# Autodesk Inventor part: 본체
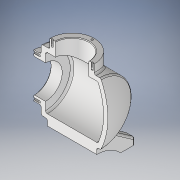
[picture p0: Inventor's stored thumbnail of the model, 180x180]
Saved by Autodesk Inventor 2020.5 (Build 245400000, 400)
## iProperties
Created: 2023-12
Part Number: 본체
Material: 일반
Document SubType Name: Modeling
Designer: 1강의실14
Density: 1 g/cm^3
Appearance: 기본값
Author: 1강의실14
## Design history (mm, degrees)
sketch "스케치1"
  geometry: L1 (-62, 0)-(-62, 36); L2 (-62, 36)-(-50, 36); L3 (-50, 36)-(-50, 50); L4 (-50, 50)-(46.336, 50); L5 (-213.2, 0)-(103.2, 0) reference; L6 (-50, 36)-(-50, 0); A1 r 113 centre (-55, 0) between (58, 0) and (-168, 0); 1 further point
  constraints: 10 end point, 4 perpendicular, 3 point on circle, 3 point on line, 1 centre point, 1 vertical
  dimensions: "d0" = 226 diameter of A1; "d1" = 62 distance from line of point (0, 0) L1; "d2" = 120 distance from line of L1 A1.start; "d3" = 50 distance between parallel lines of L5 L4; "d4" = 36 distance between parallel lines of L5 L2; "d5" = 12 distance between parallel lines of L1 L3; "d6" = 0 distance from line of L5 A1.centre
revolve "회전1" sketch "스케치1" stored, may be unused: angle "d7" = 90 deg
feature "쉘1" dims "d8" = 7
sketch "스케치2"
  geometry: C1 r 50 at (0, 0) reference; C2 r 36 at (0, 0); 1 further point
  constraints: 1 centre point, 1 coincident
  dimensions: "d9" = 72 diameter of C2
extrude "돌출1" join sketch "스케치2" distance "d10" = 12; taper "d11" = 0 deg
sketch "스케치4"
  geometry: L1 (0, -93.179)-(0, 15.53) reference; L2 (-43, -43)-(41.887, -43) reference; L3 (0, -77.65)-(0, -69.806); 3 further points
  constraints: 2 end point, 2 point on line, 1 symmetric about line
sketch "스케치5"
  geometry: L1 (-42.278, -26.694)-(-67, -62); L2 (-67, -62)-(-77, -62); L3 (-77, -62)-(-77, -38.5); L4 (-144.515, 0)-(82.419, 0) reference; L5 (-42.278, 26.694)-(-67, 62); L6 (-67, 62)-(-77, 62); L7 (-77, 62)-(-77, 38.5); L8 (-71.177, 0)-(-60, 0); A1 r 52.096 centre (-112.096, 0) between (-77, -38.5) and (-77, 38.5); 3 further points
  constraints: 14 end point, 3 point on circle, 3 point on line, 3 symmetric about line, 2 perpendicular, 1 centre point, 1 horizontal, 2 other
  dimensions: "d17" = 55 deg angle of L1 L2; "d18" = 10 distance of L1.end L2.end; "d19" = 62 distance from line of L8.start L2; "d20" = 77 distance from line of L3 point (0, 0); "d22" = 77 distance of L7.end L3.end; "d23" = 17 distance from line of L7 L8.end
extrude "돌출2" join sketch "스케치5" stored distance "d24" = 80; taper "d25" = 0 deg
sketch "스케치6"
  geometry: C1 r 36 at (0, 0) reference; 1 further point
hole "구멍1" sketch "스케치6" at (0, 0) diameter "d26" = 54; stored, may be unused: countersink angle "d30" = 90 deg, drill point angle "d32" = 0 deg; dims "d27" = 6, "d28" = 11, "d29" = 6.6, "d31" = 20
node "작업 평면2"
sketch "스케치7"
  geometry: C1 r 36 at (0, 0); 1 further point
  constraints: 1 centre point, 1 coincident
  dimensions: "d34" = 72 diameter of C1
extrude "돌출3" join sketch "스케치7" stored distance "d35" = 10; taper "d36" = 0 deg
sketch "스케치8"
  geometry: C1 r 36 at (0, 0) reference; 1 further point
hole "구멍2" sketch "스케치8" at (0, 0) diameter "d37" = 54; stored, may be unused: countersink angle "d41" = 90 deg, drill point angle "d43" = 0 deg; dims "d38" = 6, "d39" = 11, "d40" = 6.6, "d42" = 50
chamfer "모따기1" distance "d44" = 1; stored, may be unused: second distance "d45" = 2, angle "d46" = 45 deg
sketch "스케치9"
  geometry: L1 (0, 0)-(0, 32.5)
  constraints: 2 end point, 1 vertical
  dimensions: "d47" = 32.5 distance of L1.start L1.end
hole "구멍3" sketch "스케치9" at (0, 32.5) diameter "d48" = 3.242; stored, may be unused: countersink angle "d52" = 90 deg, drill point angle "d54" = 118 deg; dims "d49" = 8, "d50" = 11, "d51" = 6.6, "d53" = 10
fillet "모깎기1" dims "d58" = 3
fillet "모깎기2" dims "d59" = 3
fillet "모깎기3" dims "d60" = 3
sketch "스케치10"
  geometry: L1 (0, 0)-(0, 32.5)
  constraints: 2 end point, 1 vertical
  dimensions: "d61" = 32.5 distance of L1.start L1.end
hole "구멍4" sketch "스케치10" at (0, 32.5) diameter "d62" = 3.242; stored, may be unused: countersink angle "d66" = 90 deg, drill point angle "d68" = 118 deg; dims "d63" = 8, "d64" = 11, "d65" = 6.6, "d67" = 10
node "작업 평면3"
sketch "스케치11"
  geometry: L1 (20, 31.5)-(20, 15.5); L2 (0, 23.5)-(80, 23.5) reference; L3 (13, 31.5)-(13, 15.5); L4 (27, 15.5)-(27, 31.5); L5 (0, 0)-(0, 23.5) reference; L6 (40, -128.3)-(40, 66.3) reference; L7 (53, 15.5)-(53, 31.5); L8 (67, 31.5)-(67, 15.5); A1 r 7 centre (20, 31.5) between (27, 31.5) and (13, 31.5); A2 r 7 centre (20, 15.5) between (13, 15.5) and (27, 15.5); A3 r 7 centre (60, 15.5) between (53, 15.5) and (67, 15.5); A4 r 7 centre (60, 31.5) between (67, 31.5) and (53, 31.5); 6 further points
  constraints: 12 end point, 8 point on circle, 6 symmetric about line, 4 centre point, 4 tangent, 1 midpoint, 1 parallel, 1 perpendicular, 1 point on line, 2 other
  dimensions: "d73" = 20 distance from line of point (20, 23.5) L5; "d74" = 8 distance from line of L2 L1.end; "d76" = 14 distance between parallel lines of L4 L3
extrude "돌출4" cut sketch "스케치11" distance "d77" = 17; taper "d78" = 0 deg
sketch "스케치12"
  geometry: A1 r 7 centre (20, -15.5) between (27, -15.5) and (13, -15.5) reference; A2 r 7 centre (60, -15.5) between (67, -15.5) and (53, -15.5) reference; 1 further point
hole "구멍5" sketch "스케치12" at (20, -15.5), (60, -15.5) diameter "d79" = 9; stored, may be unused: countersink angle "d83" = 90 deg, drill point angle "d85" = 0 deg; dims "d80" = 8, "d81" = 11, "d82" = 6.6, "d84" = 10
node "작업 평면4"
sketch "스케치13"
  geometry: L1 (-62, 36)-(-62, -36) reference; L2 (-80.918, 0)-(65.507, 0) reference; L3 (36, 65)-(36, 50) reference; 2 further points
  constraints: 1 point on line, 1 other
  dimensions: "d87" = 62 distance from line of L1 point (0, 0)
feature "엠보싱1" sketch "스케치13" dims "d88" = 0.5, "d89" = 0
fillet "모깎기4" dims "d90" = 3
fillet "모깎기5" dims "d91" = 3
fillet "모깎기6" dims "d92" = 3
feature "분할1"
node "솔리드1"
pattern_circular "원형 패턴1" dims angle "d56" = 360 deg
pattern_circular "원형 패턴2" dims angle "d70" = 360 deg
mirror "미러1"
node "투영된 루프1"
node "투영된 루프2"
feature "A9D066F2-1C7D-4E18-AEED-F7BC21143FA4" dims "d26" = 54, "d27" = 6, "d28" = 11, "d29" = 6.6, "d30" = 90 deg, "d31" = 20, "d32" = 0
other parameters: "d33" = 65, "d72" = -6, "d86" = 52.25
